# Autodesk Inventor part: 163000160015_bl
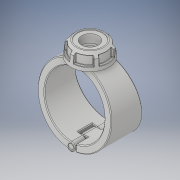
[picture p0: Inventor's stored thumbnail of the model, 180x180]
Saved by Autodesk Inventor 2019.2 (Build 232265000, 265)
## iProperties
Created: 2022-02
Part Number: 163000160015_bl
Material: Generic
Description: Plassadle Threaded 160x1 1/2''
Document SubType Name: Modeling
Designer: comp2
Density: 1 g/cm^3
Appearance: Default
Author: comp2
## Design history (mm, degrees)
derived "16300.ipt"
feature "Solid1::16300.ipt" dims "ScaleForDerivedMember" = 10
feature "Solid2::16300.ipt" dims "ScaleForDerivedMember" = 10
feature "Solid3::16300.ipt" dims "ScaleForDerivedMember" = 10
feature "Solid4::16300.ipt" dims "ScaleForDerivedMember" = 10
tag "TaggingFeature1"
body "Solid1"
body "Solid2"
body "Solid3"
body "Solid4"
other parameters: "d2" = 197 [user parameter], "d7" = 187.15 [user parameter], "d8" = 85 deg [user parameter], "d9" = 45 deg [user parameter], "d10" = 102 [user parameter], "d11" = 49 [user parameter], "d12" = 27.2895 [user parameter], "d13" = 42.84 [user parameter], "d14" = 67.2675 [user parameter], "d42" = 3.7 [user parameter], "d49" = 3.94 [user parameter], "d50" = 106 [user parameter], "d51" = 0 [user parameter], "d52" = 25.9 [user parameter], "d53" = 108.35 [user parameter], "d54" = 37.1 [user parameter], "d55" = 0 [user parameter], "d56" = 21.2 [user parameter], "d57" = 21.2 [user parameter], "d59" = 0 [user parameter], "d60" = 106 [user parameter], "d61" = 0 [user parameter], "d62" = 37.1 [user parameter], "d63" = 0 [user parameter], "d65" = 0 [user parameter], "d67" = 0 [user parameter], "d69" = 0 [user parameter], "d70" = 1 [user parameter], "d71" = 101.76 [user parameter], "d72" = 0 [user parameter], "d73" = 2 [user parameter], "d78" = 86.7 [user parameter], "d79" = 5.1 [user parameter], "d80" = 60 deg [user parameter], "d81" = 5.1 [user parameter], "d84" = 0 [user parameter], "d85" = 1 [user parameter], "d87" = 360 deg [user parameter], "d122" = 49 [user parameter], "d124" = 42.80128 [user parameter], "d125" = 1.94925 [user parameter], "d127" = 235 [user parameter], "d129" = 44.845 [user parameter], "d130" = 38.11825 [user parameter], "d131" = 31.85 [user parameter], "d132" = 45 deg [user parameter], "d133" = 22.295 [user parameter], "d134" = 22.4225 [user parameter], "d136" = 0 [user parameter], "d138" = 0 [user parameter], "d1" = 25 [user parameter], "B" = 197 [user parameter], "L" = 106 [user parameter], "E_" = 54 [user parameter], "E1" = 102 [user parameter], "H1" = 235 [user parameter], "H2" = 49 [user parameter], "H3" = 78 [user parameter], "H_costum" = 49 [user parameter], "Rp" = 44.845 [user parameter], "d128" = 38.985 [user parameter]
